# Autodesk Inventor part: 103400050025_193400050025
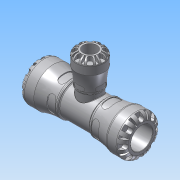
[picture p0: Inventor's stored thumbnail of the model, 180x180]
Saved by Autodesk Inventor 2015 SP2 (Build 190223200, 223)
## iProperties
Created: 2016-12
Part Number: 103400050025_193400050025
Material: PVC-Piping
Description: PLASSON REDUCING TEE 50X25X50 SERIES 1
Document SubType Name: Modeling
Designer: KIM
Mass: 664.223 g
Surface Area: 733.008 cm^2
Volume: 474.445 cm^3
Density: 1.4 g/cm^3
Appearance: Smooth - White
Author: KIM
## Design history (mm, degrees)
derived "1034.ipt"
feature "Solid1::1034.ipt"
tag "TaggingFeature1"
body "Solid1"
other parameters: "d9" = 11.25, "d11" = 85, "d12" = 62.5, "d230" = 47, "d231" = 31.25, "d232" = 7.875, "d1" = 32.76, "d3" = 62.5, "d4" = 85, "d8" = 72.25, "d13" = 9, "d14" = 9, "d15" = 0, "d17" = 360 deg, "d19" = 8 deg, "d20" = 1, "d21" = 1, "d22" = 8 deg, "d24" = 0, "d26" = 360 deg, "d33" = 8.5, "d43" = 66.3, "d51" = 0.85, "d54" = 17.5, "d55" = 11, "d57" = 17.64, "d58" = 0, "d74" = 0, "d77" = 4.16667, "d78" = 78, "d79" = 66.3, "d80" = 214, "d82" = 1, "d115" = 360 deg, "d139" = 9, "d140" = 0, "d142" = 360 deg, "d207" = 90 deg, "d209" = 20.58, "d210" = 25, "d211" = 31.25, "d212" = 47, "d213" = 39.95, "d215" = 36.66, "d216" = 2.08333, "d217" = 49, "d226" = 49, "d228" = 14.875, "d229" = 6.3, "d233" = 6.3, "d234" = 0, "d236" = 360 deg, "d238" = 8 deg, "d239" = 8 deg, "d240" = 1, "d241" = 1, "d243" = 0, "d245" = 360 deg, "d247" = 1.7, "d248" = 4.68, "d249" = 2.94, "d250" = 7.4375, "d252" = 8.75, "d253" = 5.75, "d254" = 17.64, "d255" = 0, "d257" = 360 deg, "d259" = 1, "d261" = 0, "d262" = 1.7, "d264" = 0, "d266" = 0, "d267" = 0.85, "E_" = 85, "l_" = 78, "H_" = 214, "d_1" = 25, "E_1" = 47, "l_1" = 49
